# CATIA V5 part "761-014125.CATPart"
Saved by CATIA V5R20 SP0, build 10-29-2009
Part number: 761-014125
Source: Unknown
Property "ARTICLENO": "761-014125"
Property "BOMINFO": "761-014125"
Property "CODE": "761-014125"
Property "H": "14.000"
Property "L1": "125.000"
Property "L2": "100.000"
Property "LINA": "761-014125"
Property "NB": "761-014125"
Property "NBSYN": "$CODE."
Property "NN": "761"
Property "NT": "VW/AUDI Keys"
Property "P": "0.000"
Property "SUPPLIER": "CF"
Bounding box of the stored display mesh (mm): x -62.5 to 62.5, y 0 to 14, z -11 to 11
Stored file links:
  C:\Users\Utente\Desktop\3D files 761\761-014125.CATPart
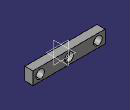
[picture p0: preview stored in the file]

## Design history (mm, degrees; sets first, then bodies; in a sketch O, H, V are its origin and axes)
Body1 "Geometry.1" (main body)
  Solid1 "761-014125.catpart": solid without history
